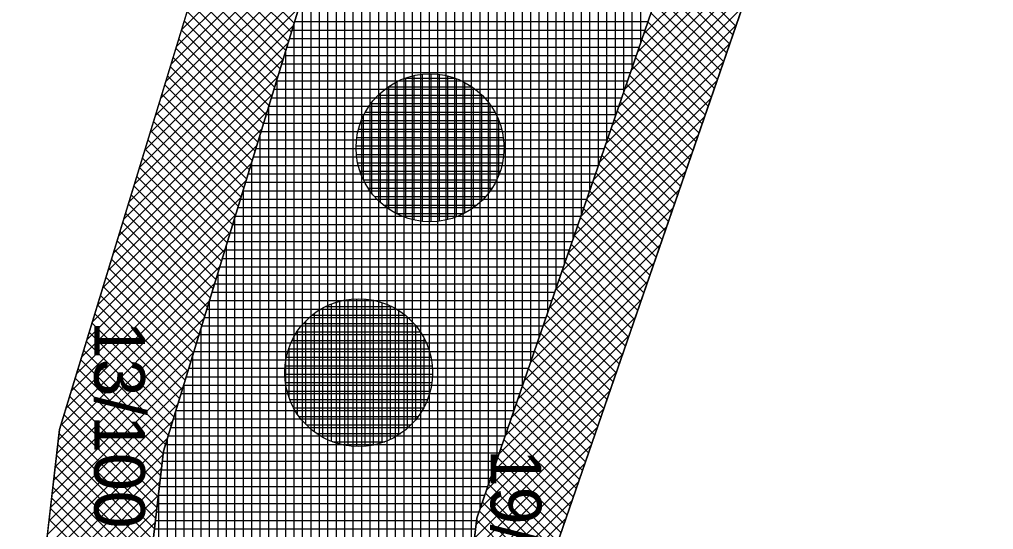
# Model space of a CAD drawing. Extents: x -565346 to -564154, y -1097386 to -1095620.
# Drawn here: x -564260.09 to -564237.04, y -1096530.2 to -1096518.14 of the extents above; entities that cross this region are included whole.
import ezdxf

# ---------------------------------------------------------------- set-up
doc = ezdxf.new("R2010")
doc.units = 0
for name, color, linetype in [('Vrstva 1', 7, 'Continuous'), ('Vrstva 13', 7, 'Continuous'), ('Vrstva 40', 7, 'Continuous'), ('Vrstva 41', 7, 'Continuous'), ('Vrstva 42', 7, 'Continuous'), ('Vrstva 43', 7, 'Continuous'), ('Vrstva 44', 7, 'Continuous')]:
    doc.layers.add(name, color=color, linetype=linetype)

msp = doc.modelspace()

# ---------------------------------------------------------------- linework, layer by layer
at = {"layer": 'Vrstva 1'}
for p, q in [((-564259.14, -1096527.84), (-564234.67, -1096447.65)), ((-564264.72, -1096575.85), (-564259.14, -1096527.84))]:
    msp.add_line(p, q, dxfattribs=at)
at = {"layer": 'Vrstva 13'}
msp.add_line((-564238.75, -1096505.56), (-564247.38, -1096530.59), dxfattribs=at)
at = {"layer": 'Vrstva 41'}
for points in [[(-564230.6, -1096442.93), (-564234.67, -1096447.65), (-564259.14, -1096527.84), (-564264.72, -1096575.85), (-564272.07, -1096706.16), (-564269.623, -1096706.334), (-564262.228, -1096576.061), (-564256.683, -1096528.354)], [(-564221.399, -1096446.296), (-564223.301, -1096445.676), (-564228.215, -1096460.758), (-564240.675, -1096505.018), (-564249.271, -1096529.938), (-564254.757, -1096576.767), (-564262.137, -1096706.758), (-564260.141, -1096706.872), (-564252.76, -1096576.88), (-564247.38, -1096530.59), (-564238.75, -1096505.56), (-564226.29, -1096461.3)]]:
    msp.add_lwpolyline(points, close=True, dxfattribs=at)
at = {"layer": 'Vrstva 42'}
for p, q in [((-564252.488, -1096514.616), (-564256.254, -1096518.382)), ((-564252.613, -1096515.023), (-564256.378, -1096518.789)), ((-564252.737, -1096515.43), (-564256.502, -1096519.196)), ((-564242.095, -1096515.263), (-564245.322, -1096518.489)), ((-564242.244, -1096515.694), (-564245.471, -1096518.921)), ((-564252.861, -1096515.838), (-564256.626, -1096519.603)), ((-564242.393, -1096516.126), (-564245.62, -1096519.353)), ((-564252.986, -1096516.245), (-564256.751, -1096520.01)), ((-564255.594, -1096516.221), (-564253.59, -1096518.225)), ((-564255.66, -1096516.437), (-564253.656, -1096518.441)), ((-564242.542, -1096516.558), (-564245.769, -1096519.784)), ((-564253.11, -1096516.652), (-564256.875, -1096520.417)), ((-564255.727, -1096516.654), (-564253.722, -1096518.658)), ((-564244.713, -1096516.723), (-564243.141, -1096518.295)), ((-564253.234, -1096517.059), (-564256.999, -1096520.824)), ((-564255.859, -1096517.087), (-564253.855, -1096519.091)), ((-564255.793, -1096516.871), (-564253.789, -1096518.875)), ((-564242.691, -1096516.989), (-564245.918, -1096520.216)), ((-564244.785, -1096516.933), (-564243.213, -1096518.505)), ((-564255.925, -1096517.304), (-564253.921, -1096519.308)), ((-564244.858, -1096517.143), (-564243.286, -1096518.715)), ((-564253.359, -1096517.466), (-564257.123, -1096521.231)), ((-564255.991, -1096517.521), (-564253.987, -1096519.525)), ((-564242.84, -1096517.421), (-564246.066, -1096520.648)), ((-564244.93, -1096517.354), (-564243.358, -1096518.926)), ((-564256.057, -1096517.738), (-564254.053, -1096519.742)), ((-564245.075, -1096517.774), (-564243.503, -1096519.346)), ((-564245.003, -1096517.564), (-564243.431, -1096519.136)), ((-564253.483, -1096517.873), (-564257.247, -1096521.638)), ((-564256.123, -1096517.954), (-564254.119, -1096519.958)), ((-564242.988, -1096517.853), (-564246.215, -1096521.08)), ((-564245.148, -1096517.985), (-564243.576, -1096519.557)), ((-564256.19, -1096518.171), (-564254.186, -1096520.175)), ((-564245.22, -1096518.195), (-564243.648, -1096519.767)), ((-564253.607, -1096518.281), (-564257.372, -1096522.045)), ((-564256.256, -1096518.388), (-564254.252, -1096520.392)), ((-564243.137, -1096518.284), (-564246.364, -1096521.512)), ((-564245.293, -1096518.405), (-564243.721, -1096519.977)), ((-564253.732, -1096518.688), (-564257.496, -1096522.452)), ((-564256.322, -1096518.604), (-564254.318, -1096520.608)), ((-564245.365, -1096518.616), (-564243.793, -1096520.188)), ((-564256.388, -1096518.821), (-564254.384, -1096520.825)), ((-564243.286, -1096518.716), (-564246.513, -1096521.943)), ((-564245.438, -1096518.826), (-564243.866, -1096520.398)), ((-564253.856, -1096519.095), (-564257.62, -1096522.859)), ((-564256.454, -1096519.038), (-564254.45, -1096521.042)), ((-564243.435, -1096519.148), (-564246.662, -1096522.375)), ((-564245.51, -1096519.036), (-564243.938, -1096520.608)), ((-564256.52, -1096519.255), (-564254.516, -1096521.258)), ((-564245.583, -1096519.247), (-564244.011, -1096520.819)), ((-564253.98, -1096519.502), (-564257.744, -1096523.266)), ((-564256.586, -1096519.471), (-564254.583, -1096521.475)), ((-564243.584, -1096519.579), (-564246.811, -1096522.807)), ((-564245.656, -1096519.457), (-564244.083, -1096521.029)), ((-564256.652, -1096519.688), (-564254.649, -1096521.692)), ((-564245.728, -1096519.667), (-564244.156, -1096521.239)), ((-564254.105, -1096519.909), (-564257.869, -1096523.673)), ((-564256.719, -1096519.905), (-564254.715, -1096521.908)), ((-564243.733, -1096520.011), (-564246.96, -1096523.239)), ((-564245.873, -1096520.088), (-564244.301, -1096521.66)), ((-564245.801, -1096519.877), (-564244.229, -1096521.45)), ((-564254.229, -1096520.316), (-564257.993, -1096524.08)), ((-564256.785, -1096520.121), (-564254.781, -1096522.125)), ((-564245.946, -1096520.298), (-564244.374, -1096521.87)), ((-564256.851, -1096520.338), (-564254.847, -1096522.342)), ((-564243.881, -1096520.443), (-564247.109, -1096523.67)), ((-564246.018, -1096520.508), (-564244.446, -1096522.081)), ((-564254.353, -1096520.724), (-564258.117, -1096524.487)), ((-564256.983, -1096520.772), (-564254.98, -1096522.775)), ((-564256.917, -1096520.555), (-564254.913, -1096522.558)), ((-564246.091, -1096520.719), (-564244.519, -1096522.291)), ((-564257.049, -1096520.988), (-564255.046, -1096522.992)), ((-564244.03, -1096520.874), (-564247.258, -1096524.102)), ((-564246.163, -1096520.929), (-564244.591, -1096522.501)), ((-564254.477, -1096521.131), (-564258.241, -1096524.894)), ((-564257.115, -1096521.205), (-564255.112, -1096523.208)), ((-564246.236, -1096521.139), (-564244.664, -1096522.712)), ((-564257.181, -1096521.422), (-564255.178, -1096523.425)), ((-564244.179, -1096521.306), (-564247.407, -1096524.534)), ((-564246.308, -1096521.35), (-564244.736, -1096522.922)), ((-564254.602, -1096521.538), (-564258.365, -1096525.302)), ((-564257.248, -1096521.638), (-564255.244, -1096523.642)), ((-564246.381, -1096521.56), (-564244.809, -1096523.132)), ((-564257.314, -1096521.855), (-564255.31, -1096523.858)), ((-564244.328, -1096521.738), (-564247.556, -1096524.966)), ((-564246.454, -1096521.77), (-564244.881, -1096523.342)), ((-564254.726, -1096521.945), (-564258.49, -1096525.709)), ((-564257.38, -1096522.072), (-564255.377, -1096524.075)), ((-564246.526, -1096521.98), (-564244.954, -1096523.553)), ((-564254.85, -1096522.352), (-564258.614, -1096526.116)), ((-564257.446, -1096522.289), (-564255.443, -1096524.292)), ((-564244.477, -1096522.17), (-564247.705, -1096525.398)), ((-564246.599, -1096522.191), (-564245.026, -1096523.763)), ((-564257.512, -1096522.505), (-564255.509, -1096524.509)), ((-564244.626, -1096522.601), (-564247.854, -1096525.829)), ((-564246.744, -1096522.611), (-564245.171, -1096524.184)), ((-564246.671, -1096522.401), (-564245.099, -1096523.973)), ((-564254.975, -1096522.759), (-564258.738, -1096526.523)), ((-564257.578, -1096522.722), (-564255.575, -1096524.725)), ((-564246.816, -1096522.822), (-564245.244, -1096524.394)), ((-564257.644, -1096522.939), (-564255.641, -1096524.942)), ((-564244.774, -1096523.033), (-564248.003, -1096526.261)), ((-564246.889, -1096523.032), (-564245.316, -1096524.604)), ((-564255.099, -1096523.167), (-564258.862, -1096526.93)), ((-564257.71, -1096523.155), (-564255.707, -1096525.159)), ((-564246.961, -1096523.242), (-564245.389, -1096524.815)), ((-564257.777, -1096523.372), (-564255.773, -1096525.375)), ((-564244.923, -1096523.465), (-564248.152, -1096526.693)), ((-564247.034, -1096523.453), (-564245.461, -1096525.025)), ((-564255.223, -1096523.574), (-564258.986, -1096527.337)), ((-564257.843, -1096523.589), (-564255.84, -1096525.592)), ((-564247.106, -1096523.663), (-564245.534, -1096525.235)), ((-564255.348, -1096523.981), (-564259.111, -1096527.744)), ((-564257.909, -1096523.806), (-564255.906, -1096525.809)), ((-564245.072, -1096523.896), (-564248.301, -1096527.125)), ((-564247.179, -1096523.873), (-564245.606, -1096525.446)), ((-564258.041, -1096524.239), (-564256.038, -1096526.242)), ((-564257.975, -1096524.022), (-564255.972, -1096526.025)), ((-564247.251, -1096524.083), (-564245.679, -1096525.656)), ((-564255.472, -1096524.388), (-564259.168, -1096528.084)), ((-564258.107, -1096524.456), (-564256.104, -1096526.459)), ((-564245.221, -1096524.328), (-564248.45, -1096527.557)), ((-564247.324, -1096524.294), (-564245.751, -1096525.866)), ((-564258.173, -1096524.672), (-564256.17, -1096526.675)), ((-564247.397, -1096524.504), (-564245.824, -1096526.077)), ((-564255.596, -1096524.795), (-564259.206, -1096528.404)), ((-564258.24, -1096524.889), (-564256.237, -1096526.892)), ((-564245.37, -1096524.76), (-564248.598, -1096527.988)), ((-564247.542, -1096524.925), (-564245.969, -1096526.497)), ((-564247.469, -1096524.714), (-564245.896, -1096526.287)), ((-564258.306, -1096525.106), (-564256.303, -1096527.109)), ((-564247.614, -1096525.135), (-564246.041, -1096526.708)), ((-564255.721, -1096525.202), (-564259.243, -1096528.725)), ((-564258.372, -1096525.323), (-564256.369, -1096527.325)), ((-564245.519, -1096525.191), (-564248.747, -1096528.42)), ((-564247.687, -1096525.345), (-564246.114, -1096526.918)), ((-564255.845, -1096525.61), (-564259.28, -1096529.045)), ((-564258.438, -1096525.539), (-564256.435, -1096527.542)), ((-564247.759, -1096525.556), (-564246.186, -1096527.128)), ((-564258.504, -1096525.756), (-564256.501, -1096527.759)), ((-564245.667, -1096525.623), (-564248.896, -1096528.852)), ((-564247.832, -1096525.766), (-564246.259, -1096527.339)), ((-564255.969, -1096526.017), (-564259.317, -1096529.365)), ((-564258.57, -1096525.973), (-564256.567, -1096527.975)), ((-564245.816, -1096526.055), (-564249.045, -1096529.284)), ((-564247.904, -1096525.976), (-564246.332, -1096527.549)), ((-564258.636, -1096526.189), (-564256.634, -1096528.192)), ((-564247.977, -1096526.186), (-564246.404, -1096527.759)), ((-564256.094, -1096526.424), (-564259.354, -1096529.685)), ((-564258.702, -1096526.406), (-564256.69, -1096528.418)), ((-564245.965, -1096526.486), (-564249.194, -1096529.715)), ((-564248.049, -1096526.397), (-564246.477, -1096527.97)), ((-564258.769, -1096526.623), (-564256.72, -1096528.671)), ((-564248.122, -1096526.607), (-564246.549, -1096528.18)), ((-564256.218, -1096526.831), (-564259.392, -1096530.005)), ((-564258.835, -1096526.84), (-564256.749, -1096528.925)), ((-564246.114, -1096526.918), (-564249.289, -1096530.093)), ((-564248.195, -1096526.817), (-564246.622, -1096528.39)), ((-564258.901, -1096527.056), (-564256.779, -1096529.178)), ((-564248.267, -1096527.028), (-564246.694, -1096528.601)), ((-564256.342, -1096527.238), (-564259.429, -1096530.325)), ((-564258.967, -1096527.273), (-564256.808, -1096529.432)), ((-564246.263, -1096527.35), (-564249.327, -1096530.414)), ((-564248.412, -1096527.448), (-564246.839, -1096529.021)), ((-564248.34, -1096527.238), (-564246.767, -1096528.811)), ((-564256.467, -1096527.645), (-564259.466, -1096530.645)), ((-564259.033, -1096527.49), (-564256.838, -1096529.685)), ((-564248.485, -1096527.659), (-564246.912, -1096529.232)), ((-564259.099, -1096527.706), (-564256.867, -1096529.938)), ((-564246.412, -1096527.781), (-564249.364, -1096530.734)), ((-564248.557, -1096527.869), (-564246.984, -1096529.442)), ((-564256.591, -1096528.053), (-564259.503, -1096530.965)), ((-564259.151, -1096527.937), (-564256.897, -1096530.192)), ((-564248.63, -1096528.079), (-564247.057, -1096529.652)), ((-564259.181, -1096528.191), (-564256.926, -1096530.445)), ((-564246.56, -1096528.213), (-564249.402, -1096531.054)), ((-564248.702, -1096528.289), (-564247.129, -1096529.863)), ((-564256.693, -1096528.437), (-564259.54, -1096531.285)), ((-564259.21, -1096528.444), (-564256.956, -1096530.699)), ((-564248.775, -1096528.5), (-564247.202, -1096530.073)), ((-564256.73, -1096528.757), (-564259.578, -1096531.605)), ((-564259.24, -1096528.697), (-564256.985, -1096530.952)), ((-564246.709, -1096528.645), (-564249.439, -1096531.375)), ((-564248.847, -1096528.71), (-564247.274, -1096530.283)), ((-564256.767, -1096529.077), (-564259.615, -1096531.925)), ((-564259.269, -1096528.951), (-564257.014, -1096531.205)), ((-564246.858, -1096529.076), (-564249.477, -1096531.695)), ((-564248.92, -1096528.92), (-564247.347, -1096530.494)), ((-564259.299, -1096529.204), (-564257.044, -1096531.459)), ((-564248.993, -1096529.131), (-564247.396, -1096530.727)), ((-564256.804, -1096529.397), (-564259.652, -1096532.245)), ((-564259.328, -1096529.457), (-564257.073, -1096531.712)), ((-564247.007, -1096529.508), (-564249.514, -1096532.016)), ((-564249.065, -1096529.341), (-564247.425, -1096530.981)), ((-564256.841, -1096529.717), (-564259.689, -1096532.565)), ((-564259.357, -1096529.711), (-564257.103, -1096531.966)), ((-564249.21, -1096529.762), (-564247.484, -1096531.487)), ((-564249.138, -1096529.551), (-564247.455, -1096531.234)), ((-564259.387, -1096529.964), (-564257.132, -1096532.219)), ((-564247.156, -1096529.94), (-564249.552, -1096532.336)), ((-564249.276, -1096529.979), (-564247.514, -1096531.741)), ((-564256.879, -1096530.037), (-564259.726, -1096532.885))]:
    msp.add_line(p, q, dxfattribs=at)
at = {"layer": 'Vrstva 43'}
for p, q in [((-564245.39, -1096518.687), (-564245.39, -1096491.368)), ((-564245.59, -1096519.267), (-564245.59, -1096492.024)), ((-564245.79, -1096519.847), (-564245.79, -1096492.679)), ((-564245.99, -1096520.426), (-564245.99, -1096493.334)), ((-564246.19, -1096521.006), (-564246.19, -1096493.989)), ((-564246.39, -1096521.586), (-564246.39, -1096494.644)), ((-564246.59, -1096522.166), (-564246.59, -1096495.299)), ((-564246.79, -1096522.746), (-564246.79, -1096495.954)), ((-564246.99, -1096523.325), (-564246.99, -1096496.609)), ((-564247.19, -1096523.905), (-564247.19, -1096497.264)), ((-564247.39, -1096524.485), (-564247.39, -1096497.919)), ((-564247.59, -1096525.065), (-564247.59, -1096498.574)), ((-564247.79, -1096525.645), (-564247.79, -1096499.229)), ((-564247.99, -1096526.224), (-564247.99, -1096499.884)), ((-564248.19, -1096526.804), (-564248.19, -1096500.539)), ((-564248.39, -1096527.384), (-564248.39, -1096501.194)), ((-564248.59, -1096527.964), (-564248.59, -1096501.849)), ((-564248.79, -1096528.544), (-564248.79, -1096502.504)), ((-564248.99, -1096529.123), (-564248.99, -1096503.159)), ((-564249.19, -1096529.703), (-564249.19, -1096503.814)), ((-564249.39, -1096530.954), (-564249.39, -1096504.469)), ((-564249.59, -1096532.661), (-564249.59, -1096505.124)), ((-564249.79, -1096534.368), (-564249.79, -1096505.779)), ((-564249.99, -1096536.075), (-564249.99, -1096506.434)), ((-564250.19, -1096537.783), (-564250.19, -1096507.089)), ((-564250.39, -1096539.49), (-564250.39, -1096507.744)), ((-564250.59, -1096541.197), (-564250.59, -1096508.399)), ((-564250.79, -1096542.904), (-564250.79, -1096509.054)), ((-564250.99, -1096544.612), (-564250.99, -1096509.709)), ((-564251.19, -1096546.319), (-564251.19, -1096510.364)), ((-564251.39, -1096548.026), (-564251.39, -1096511.019)), ((-564251.59, -1096549.733), (-564251.59, -1096511.674)), ((-564251.79, -1096551.44), (-564251.79, -1096512.329)), ((-564251.99, -1096553.148), (-564251.99, -1096512.984)), ((-564252.19, -1096554.855), (-564252.19, -1096513.639)), ((-564252.39, -1096556.562), (-564252.39, -1096514.294)), ((-564252.59, -1096558.269), (-564252.59, -1096514.949)), ((-564252.79, -1096559.977), (-564252.79, -1096515.604)), ((-564252.99, -1096561.684), (-564252.99, -1096516.259)), ((-564253.19, -1096563.391), (-564253.19, -1096516.914)), ((-564253.39, -1096565.098), (-564253.39, -1096517.569)), ((-564253.59, -1096566.805), (-564253.59, -1096518.224)), ((-564253.58, -1096518.19), (-564245.219, -1096518.19)), ((-564253.641, -1096518.39), (-564245.288, -1096518.39)), ((-564253.702, -1096518.59), (-564245.357, -1096518.59)), ((-564253.79, -1096568.513), (-564253.79, -1096518.879)), ((-564253.763, -1096518.79), (-564245.426, -1096518.79)), ((-564253.824, -1096518.99), (-564245.495, -1096518.99)), ((-564253.946, -1096519.39), (-564245.633, -1096519.39)), ((-564253.885, -1096519.19), (-564245.564, -1096519.19)), ((-564254.007, -1096519.59), (-564245.702, -1096519.59)), ((-564253.99, -1096570.22), (-564253.99, -1096519.534)), ((-564254.068, -1096519.79), (-564245.771, -1096519.79)), ((-564254.129, -1096519.99), (-564245.839, -1096519.99)), ((-564254.19, -1096571.927), (-564254.19, -1096520.189)), ((-564254.19, -1096520.19), (-564245.908, -1096520.19)), ((-564254.251, -1096520.39), (-564245.977, -1096520.39)), ((-564254.312, -1096520.59), (-564246.046, -1096520.59)), ((-564254.435, -1096520.99), (-564246.184, -1096520.99)), ((-564254.39, -1096573.634), (-564254.39, -1096520.844)), ((-564254.373, -1096520.79), (-564246.115, -1096520.79)), ((-564254.496, -1096521.19), (-564246.253, -1096521.19)), ((-564254.557, -1096521.39), (-564246.322, -1096521.39)), ((-564254.618, -1096521.59), (-564246.391, -1096521.59)), ((-564254.59, -1096575.341), (-564254.59, -1096521.499)), ((-564254.679, -1096521.79), (-564246.46, -1096521.79)), ((-564254.79, -1096577.348), (-564254.79, -1096522.154)), ((-564254.74, -1096521.99), (-564246.529, -1096521.99)), ((-564254.862, -1096522.39), (-564246.667, -1096522.39)), ((-564254.801, -1096522.19), (-564246.598, -1096522.19)), ((-564254.923, -1096522.59), (-564246.736, -1096522.59)), ((-564254.99, -1096580.871), (-564254.99, -1096522.809)), ((-564254.984, -1096522.79), (-564246.805, -1096522.79)), ((-564255.045, -1096522.99), (-564246.874, -1096522.99)), ((-564255.106, -1096523.19), (-564246.943, -1096523.19)), ((-564255.19, -1096584.394), (-564255.19, -1096523.464)), ((-564255.167, -1096523.39), (-564247.012, -1096523.39)), ((-564255.228, -1096523.59), (-564247.081, -1096523.59)), ((-564255.351, -1096523.99), (-564247.219, -1096523.99)), ((-564255.289, -1096523.79), (-564247.15, -1096523.79)), ((-564255.412, -1096524.19), (-564247.288, -1096524.19)), ((-564255.39, -1096587.917), (-564255.39, -1096524.119)), ((-564255.473, -1096524.39), (-564247.357, -1096524.39)), ((-564255.534, -1096524.59), (-564247.426, -1096524.59)), ((-564255.595, -1096524.79), (-564247.495, -1096524.79)), ((-564255.59, -1096591.439), (-564255.59, -1096524.774)), ((-564255.656, -1096524.99), (-564247.564, -1096524.99)), ((-564255.778, -1096525.39), (-564247.702, -1096525.39)), ((-564255.717, -1096525.19), (-564247.633, -1096525.19)), ((-564255.839, -1096525.59), (-564247.771, -1096525.59)), ((-564255.79, -1096594.962), (-564255.79, -1096525.429)), ((-564255.9, -1096525.79), (-564247.84, -1096525.79)), ((-564255.961, -1096525.99), (-564247.909, -1096525.99)), ((-564256.022, -1096526.19), (-564247.978, -1096526.19)), ((-564255.99, -1096598.485), (-564255.99, -1096526.084)), ((-564256.083, -1096526.39), (-564248.047, -1096526.39)), ((-564256.19, -1096602.008), (-564256.19, -1096526.739)), ((-564256.144, -1096526.59), (-564248.116, -1096526.59)), ((-564256.267, -1096526.99), (-564248.254, -1096526.99)), ((-564256.205, -1096526.79), (-564248.185, -1096526.79)), ((-564256.328, -1096527.19), (-564248.323, -1096527.19)), ((-564256.39, -1096605.531), (-564256.39, -1096527.394)), ((-564256.389, -1096527.39), (-564248.392, -1096527.39)), ((-564256.45, -1096527.59), (-564248.461, -1096527.59)), ((-564256.511, -1096527.79), (-564248.53, -1096527.79)), ((-564256.59, -1096609.053), (-564256.59, -1096528.049)), ((-564256.572, -1096527.99), (-564248.599, -1096527.99)), ((-564256.633, -1096528.19), (-564248.668, -1096528.19)), ((-564256.71, -1096528.59), (-564248.806, -1096528.59)), ((-564256.687, -1096528.39), (-564248.737, -1096528.39)), ((-564256.734, -1096528.79), (-564248.875, -1096528.79)), ((-564256.757, -1096528.99), (-564248.944, -1096528.99)), ((-564256.79, -1096612.576), (-564256.79, -1096529.275)), ((-564256.78, -1096529.19), (-564249.013, -1096529.19)), ((-564256.803, -1096529.39), (-564249.082, -1096529.39)), ((-564256.827, -1096529.59), (-564249.151, -1096529.59)), ((-564256.873, -1096529.99), (-564249.277, -1096529.99)), ((-564256.85, -1096529.79), (-564249.22, -1096529.79)), ((-564256.896, -1096530.19), (-564249.301, -1096530.19))]:
    msp.add_line(p, q, dxfattribs=at)
msp.add_lwpolyline([(-564261.274, -1096726.84), (-564260.141, -1096706.872), (-564262.137, -1096706.758), (-564254.757, -1096576.767), (-564249.271, -1096529.938), (-564240.675, -1096505.018), (-564228.215, -1096460.758), (-564223.301, -1096445.676), (-564221.399, -1096446.296), (-564218.92, -1096438.69), (-564229.82, -1096442.05), (-564230.6, -1096442.93), (-564256.683, -1096528.354), (-564262.228, -1096576.061), (-564269.623, -1096706.334), (-564272.07, -1096706.16), (-564273.28, -1096725.96)], dxfattribs=at)
at = {"layer": 'Vrstva 44'}
for p, q in [((-564251.15, -1096522.741), (-564251.15, -1096519.606)), ((-564250.97, -1096519.53), (-564249.78, -1096519.53)), ((-564250.95, -1096522.824), (-564250.95, -1096519.523)), ((-564250.75, -1096522.883), (-564250.75, -1096519.467)), ((-564250.55, -1096522.914), (-564250.55, -1096519.434)), ((-564250.35, -1096522.922), (-564250.35, -1096519.424)), ((-564250.15, -1096522.908), (-564250.15, -1096519.44)), ((-564249.95, -1096522.871), (-564249.95, -1096519.478)), ((-564249.75, -1096522.808), (-564249.75, -1096519.541)), ((-564251.359, -1096519.73), (-564249.387, -1096519.73)), ((-564251.35, -1096522.625), (-564251.35, -1096519.723)), ((-564249.55, -1096522.716), (-564249.55, -1096519.63)), ((-564249.35, -1096522.592), (-564249.35, -1096519.757)), ((-564251.603, -1096519.93), (-564249.143, -1096519.93)), ((-564251.55, -1096522.468), (-564251.55, -1096519.879)), ((-564249.15, -1096522.422), (-564249.15, -1096519.924)), ((-564251.778, -1096520.13), (-564248.972, -1096520.13)), ((-564251.75, -1096522.252), (-564251.75, -1096520.096)), ((-564248.95, -1096522.188), (-564248.95, -1096520.159)), ((-564251.999, -1096520.53), (-564248.749, -1096520.53)), ((-564251.95, -1096521.932), (-564251.95, -1096520.415)), ((-564251.905, -1096520.33), (-564248.841, -1096520.33)), ((-564248.75, -1096521.822), (-564248.75, -1096520.527)), ((-564252.066, -1096520.73), (-564248.683, -1096520.73)), ((-564252.106, -1096520.93), (-564248.642, -1096520.93)), ((-564252.122, -1096521.13), (-564248.625, -1096521.13)), ((-564252.115, -1096521.33), (-564248.632, -1096521.33)), ((-564252.086, -1096521.53), (-564248.663, -1096521.53)), ((-564252.033, -1096521.73), (-564248.717, -1096521.73)), ((-564251.951, -1096521.93), (-564248.796, -1096521.93)), ((-564251.838, -1096522.13), (-564248.91, -1096522.13)), ((-564251.687, -1096522.33), (-564249.062, -1096522.33)), ((-564251.479, -1096522.53), (-564249.271, -1096522.53)), ((-564251.175, -1096522.73), (-564249.577, -1096522.73)), ((-564252.849, -1096524.93), (-564251.283, -1096524.93)), ((-564252.71, -1096528.12), (-564252.71, -1096524.868)), ((-564252.51, -1096528.185), (-564252.51, -1096524.803)), ((-564252.31, -1096528.225), (-564252.31, -1096524.763)), ((-564252.11, -1096528.243), (-564252.11, -1096524.747)), ((-564251.91, -1096528.236), (-564251.91, -1096524.752)), ((-564251.71, -1096528.206), (-564251.71, -1096524.78)), ((-564251.51, -1096528.152), (-564251.51, -1096524.836)), ((-564251.31, -1096528.073), (-564251.31, -1096524.917)), ((-564253.158, -1096525.13), (-564250.969, -1096525.13)), ((-564253.11, -1096527.895), (-564253.11, -1096525.092)), ((-564252.91, -1096528.024), (-564252.91, -1096524.964)), ((-564251.11, -1096527.959), (-564251.11, -1096525.028)), ((-564253.371, -1096525.33), (-564250.76, -1096525.33)), ((-564253.31, -1096527.721), (-564253.31, -1096525.268)), ((-564250.91, -1096527.808), (-564250.91, -1096525.181)), ((-564250.71, -1096527.599), (-564250.71, -1096525.387)), ((-564253.522, -1096525.53), (-564250.605, -1096525.53)), ((-564253.51, -1096527.478), (-564253.51, -1096525.511)), ((-564253.637, -1096525.73), (-564250.492, -1096525.73)), ((-564250.51, -1096527.295), (-564250.51, -1096525.693)), ((-564253.72, -1096525.93), (-564250.409, -1096525.93)), ((-564253.71, -1096527.085), (-564253.71, -1096525.9)), ((-564253.774, -1096526.13), (-564250.353, -1096526.13)), ((-564253.812, -1096526.53), (-564250.317, -1096526.53)), ((-564253.805, -1096526.33), (-564250.324, -1096526.33)), ((-564253.798, -1096526.73), (-564250.332, -1096526.73)), ((-564253.758, -1096526.93), (-564250.37, -1096526.93)), ((-564253.692, -1096527.13), (-564250.435, -1096527.13)), ((-564253.6, -1096527.33), (-564250.529, -1096527.33)), ((-564253.473, -1096527.53), (-564250.655, -1096527.53)), ((-564253.301, -1096527.73), (-564250.828, -1096527.73)), ((-564253.061, -1096527.93), (-564251.067, -1096527.93)), ((-564252.682, -1096528.13), (-564251.445, -1096528.13))]:
    msp.add_line(p, q, dxfattribs=at)
for centre in [(-564250.374, -1096521.174), (-564252.064, -1096526.494)]:
    msp.add_circle(centre, 1.75, dxfattribs=at)

# ---------------------------------------------------------------- texts
at = {"layer": 'Vrstva 40'}
for s, p in [('13/100', (-564258.32, -1096525.27)), ('19/100', (-564248.94, -1096528.3))]:
    msp.add_text(s, height=1.2, rotation=270, dxfattribs=at).set_placement(p)

doc.saveas('drawing.dxf')
